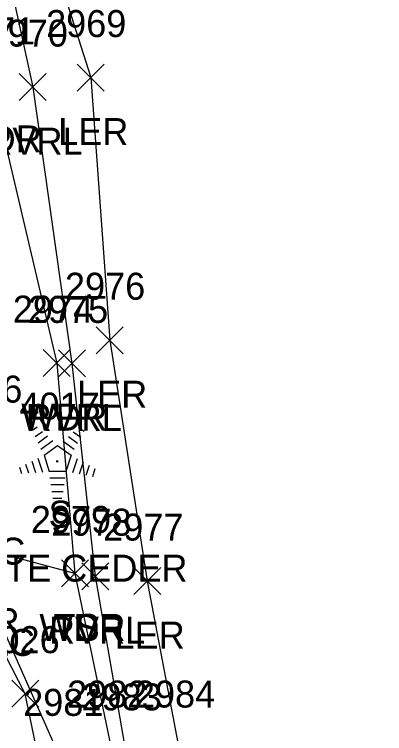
# Model space of a CAD drawing. Extents: x 1461855 to 1464118, y 556196 to 557441.
# Drawn here: x 1462162 to 1462189.5, y 556614 to 556667.3 of the extents above; entities that cross this region are included whole.
import ezdxf

# ---------------------------------------------------------------- set-up
doc = ezdxf.new("R2010")
doc.units = 0
for name, color, linetype in [('L_A', 7, 'Continuous'), ('L_C', 7, 'Continuous'), ('L_I', 7, 'Continuous'), ('L_TIC', 7, 'Continuous'), ('LARO', 7, 'Continuous'), ('LAWA', 7, 'Continuous'), ('LAWE', 7, 'Continuous'), ('LELB', 7, 'Continuous'), ('LTC', 7, 'Continuous'), ('LW', 7, 'Continuous')]:
    doc.layers.add(name, color=color, linetype=linetype)

msp = doc.modelspace()

# ---------------------------------------------------------------- linework, layer by layer
at = {"layer": 'L_TIC'}
for points in [[(1462166.682, 556661.613), (1462168.682, 556663.613)], [(1462168.682, 556661.613), (1462166.682, 556663.613)], [(1462162.376, 556660.905), (1462164.376, 556662.905)], [(1462164.376, 556660.905), (1462162.376, 556662.905)], [(1462168.082, 556642.16), (1462170.082, 556644.16)], [(1462170.082, 556642.16), (1462168.082, 556644.16)], [(1462164.164, 556640.464), (1462166.164, 556642.464)], [(1462166.164, 556640.464), (1462164.164, 556642.464)], [(1462165.279, 556640.444), (1462167.279, 556642.444)], [(1462167.279, 556640.444), (1462165.279, 556642.444)], [(1462165.507, 556624.891), (1462167.507, 556626.891)], [(1462167.507, 556624.891), (1462165.507, 556626.891)], [(1462165.507, 556624.891), (1462167.507, 556626.891)], [(1462167.507, 556624.891), (1462165.507, 556626.891)], [(1462167.012, 556624.686), (1462169.012, 556626.686)], [(1462169.012, 556624.686), (1462167.012, 556626.686)], [(1462170.862, 556624.321), (1462172.862, 556626.321)], [(1462172.862, 556624.321), (1462170.862, 556626.321)], [(1462161.82, 556615.984), (1462163.82, 556617.984)], [(1462163.82, 556615.984), (1462161.82, 556617.984)]]:
    msp.add_lwpolyline(points, dxfattribs=at)
at = {"layer": 'LARO'}
msp.add_lwpolyline([(1462153.543, 556698.226), (1462159.529, 556693.305), (1462162.233, 556679.751), (1462167.682, 556662.613), (1462169.082, 556643.16), (1462171.862, 556625.321), (1462174.213, 556612.956), (1462176.476, 556601.682), (1462174.457, 556597.693), (1462183.325, 556580.689), (1462181.304, 556562.472), (1462189.463, 556550.975), (1462182.605, 556534.635)], dxfattribs=at)
at = {"layer": 'LAWA'}
msp.add_lwpolyline([(1462144.486, 556687.662), (1462148.927, 556688.411), (1462158.302, 556680.826), (1462160.296, 556662.064), (1462165.164, 556641.464), (1462166.507, 556625.891), (1462158.371, 556628.049), (1462154.015, 556627.718), (1462147.126, 556625.455), (1462144.242, 556624.514), (1462143.044, 556630.161)], dxfattribs=at)
at = {"layer": 'LAWE'}
msp.add_lwpolyline([(1462157.004, 556715.519), (1462153.543, 556698.226), (1462154.791, 556691.267), (1462159.421, 556679.928), (1462163.376, 556661.905), (1462166.279, 556641.444), (1462168.012, 556625.686), (1462170.255, 556612.748), (1462171.886, 556604.258), (1462166.942, 556603.106), (1462170.42, 556590.593), (1462173.572, 556576.55), (1462178.747, 556561.813), (1462182.208, 556550.438), (1462181.653, 556545.019), (1462176.294, 556542.787), (1462165.32, 556537.287)], dxfattribs=at)
at = {"layer": 'LELB'}
for points in [[(1462148.927, 556688.411), (1462148.332, 556679.235), (1462150.759, 556658.223), (1462154.021, 556642.891), (1462158.371, 556628.049), (1462165.363, 556612.34), (1462167.802, 556604.927)], [(1462166.507, 556625.891), (1462169.186, 556612.955), (1462171.305, 556604.927), (1462167.802, 556604.927)]]:
    msp.add_lwpolyline(points, dxfattribs=at)
at = {"layer": 'LTC'}
for p, q in [((1462163.361, 556636.489), (1462163.716, 556636.747)), ((1462166.76, 556636.73), (1462167.179, 556636.425)), ((1462163.571, 556636.024), (1462164.1, 556636.408)), ((1462166.388, 556636.381), (1462166.938, 556635.982)), ((1462163.78, 556635.558), (1462164.484, 556636.069)), ((1462163.99, 556635.092), (1462164.868, 556635.73)), ((1462165.646, 556635.685), (1462166.456, 556635.096)), ((1462166.018, 556636.033), (1462166.697, 556635.539)), ((1462164.215, 556634.637), (1462165.226, 556635.372)), ((1462165.226, 556635.372), (1462166.223, 556634.647)), ((1462164.215, 556634.637), (1462164.602, 556633.444)), ((1462166.223, 556634.647), (1462165.832, 556633.444)), ((1462162.849, 556633.985), (1462163.061, 556633.334)), ((1462163.305, 556634.202), (1462163.576, 556633.366)), ((1462163.76, 556634.418), (1462164.091, 556633.399)), ((1462166.661, 556634.376), (1462166.323, 556633.336)), ((1462167.105, 556634.126), (1462166.818, 556633.241)), ((1462162.394, 556633.769), (1462162.546, 556633.301)), ((1462165.832, 556633.444), (1462164.602, 556633.444)), ((1462167.55, 556633.876), (1462167.313, 556633.146)), ((1462167.994, 556633.625), (1462167.808, 556633.051)), ((1462165.794, 556632.944), (1462164.649, 556632.944)), ((1462165.71, 556632.444), (1462164.722, 556632.444)), ((1462165.626, 556631.944), (1462164.795, 556631.944)), ((1462165.543, 556631.444), (1462164.868, 556631.444))]:
    msp.add_line(p, q, dxfattribs=at)
at = {"layer": 'LW'}
msp.add_lwpolyline([(1462165.028, 556537.928), (1462178.105, 556543.807), (1462180.56, 556544.806), (1462181.677, 556547.712), (1462181.204, 556550.448), (1462180.21, 556555.376), (1462173.165, 556575.068), (1462168.671, 556591.797), (1462165.687, 556603.179), (1462162.82, 556616.984), (1462158.792, 556624.78), (1462153.945, 556627.528), (1462148.568, 556625.245), (1462146.516, 556624.825), (1462140.968, 556623.1)], dxfattribs=at)

# ---------------------------------------------------------------- texts
at = {"layer": 'L_A'}
for s, p in [('LER', (1462165.265, 556657.613)), ('WDR', (1462157.659, 556657.064)), ('RVRL', (1462159.943, 556656.905)), ('LER', (1462166.665, 556638.16)), ('WDR', (1462162.526, 556636.464)), ('RVRL', (1462162.846, 556636.444)), ('S', (1462164.552, 556629.281)), ('WDR', (1462163.869, 556620.891)), ('TS', (1462164.916, 556620.891)), ('RVRL', (1462164.579, 556620.686)), ('LER', (1462169.444, 556620.321)), ('WALLC', (1462154.327, 556619.78))]:
    msp.add_text(s, height=2, dxfattribs=at).set_placement(p)
at = {"layer": 'L_C'}
for s, p in [('6 LOC', (1462155.101, 556626.54)), ('6 WHITE CEDER', (1462153.898, 556625.281)), ('6 WHITE CEDER', (1462141.453, 556621.336))]:
    msp.add_text(s, height=2, dxfattribs=at).set_placement(p)
at = {"layer": 'L_I'}
for s, p in [('2969', (1462164.367, 556665.613)), ('2971', (1462157.603, 556665.064)), ('2970', (1462160.029, 556664.905)), ('2976', (1462165.767, 556646.16)), ('2974', (1462161.904, 556644.464)), ('2975', (1462163.019, 556644.444)), ('4016', (1462156.66, 556638.54)), ('4017', (1462162.394, 556637.281)), ('2979', (1462163.239, 556628.891)), ('2979', (1462163.239, 556628.891)), ('2978', (1462164.752, 556628.686)), ('2977', (1462168.602, 556628.321)), ('3026', (1462159.426, 556619.984)), ('2982', (1462165.926, 556615.955)), ('2984', (1462170.953, 556615.956)), ('2983', (1462166.995, 556615.748)), ('2981', (1462162.67, 556615.34))]:
    msp.add_text(s, height=2, dxfattribs=at).set_placement(p)
at = {"layer": 'LTC'}
msp.add_text('.', height=1.037, rotation=270, dxfattribs=at).set_placement((1462165.109, 556634.385))

doc.saveas('drawing.dxf')
